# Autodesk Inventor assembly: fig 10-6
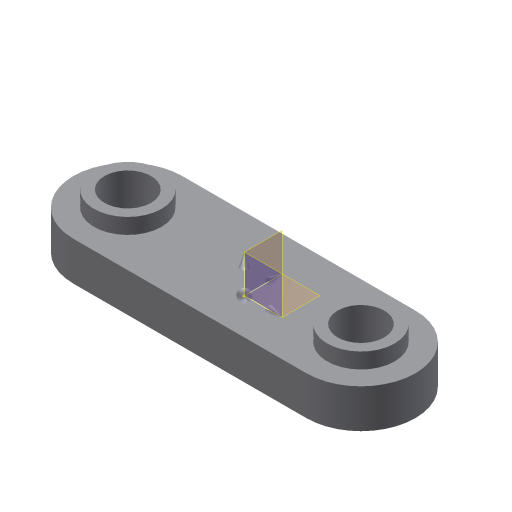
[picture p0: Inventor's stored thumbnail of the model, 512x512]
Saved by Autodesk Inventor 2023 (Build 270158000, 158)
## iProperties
Created: 2010-08
Part Number: fig 10-6
Document SubType Name: Assembly
Designer: CADSoft
Author: CADSoft
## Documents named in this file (2)
- D:\PROJECTS\Project 2022\Autodesk Inventor For Professional 2023\RESOURCES INVENTOR 2023\RESOURCES INVENTOR 2023\Inventor_2023_Part\Inventor_2023_Part\c10_Inv_2023_prt\fig 10-6.iam
- D:\PROJECTS\Project 2022\Autodesk Inventor For Professional 2023\RESOURCES INVENTOR 2023\RESOURCES INVENTOR 2023\Inventor_2023_Part\Inventor_2023_Part\c10_Inv_2023_prt\Part6.ipt
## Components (1 placed, 1 different names)
1. Part6:1
